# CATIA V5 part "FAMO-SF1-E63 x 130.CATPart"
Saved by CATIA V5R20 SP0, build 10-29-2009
Part number: FAMO-SF1-E63 x 130
Definition: NONE
Nomenclature: FAMO-SF1-E63 x 130
Source: Unknown
Description: FAMO-SF1-E63 x 130
Bounding box of the stored display mesh (mm): x -82 to 48, y -46 to 46, z -46 to 46
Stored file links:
  C:\Users\Utente\Desktop\IO LAVORO\3D X SITO CF\X SITO\FAMO\FAMO-SF1-E63 x 130.CATPart

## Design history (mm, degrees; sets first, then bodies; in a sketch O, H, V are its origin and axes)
Body1 "FAMO-SF1-E63 x 130" (main body)
  Solid1: solid without history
